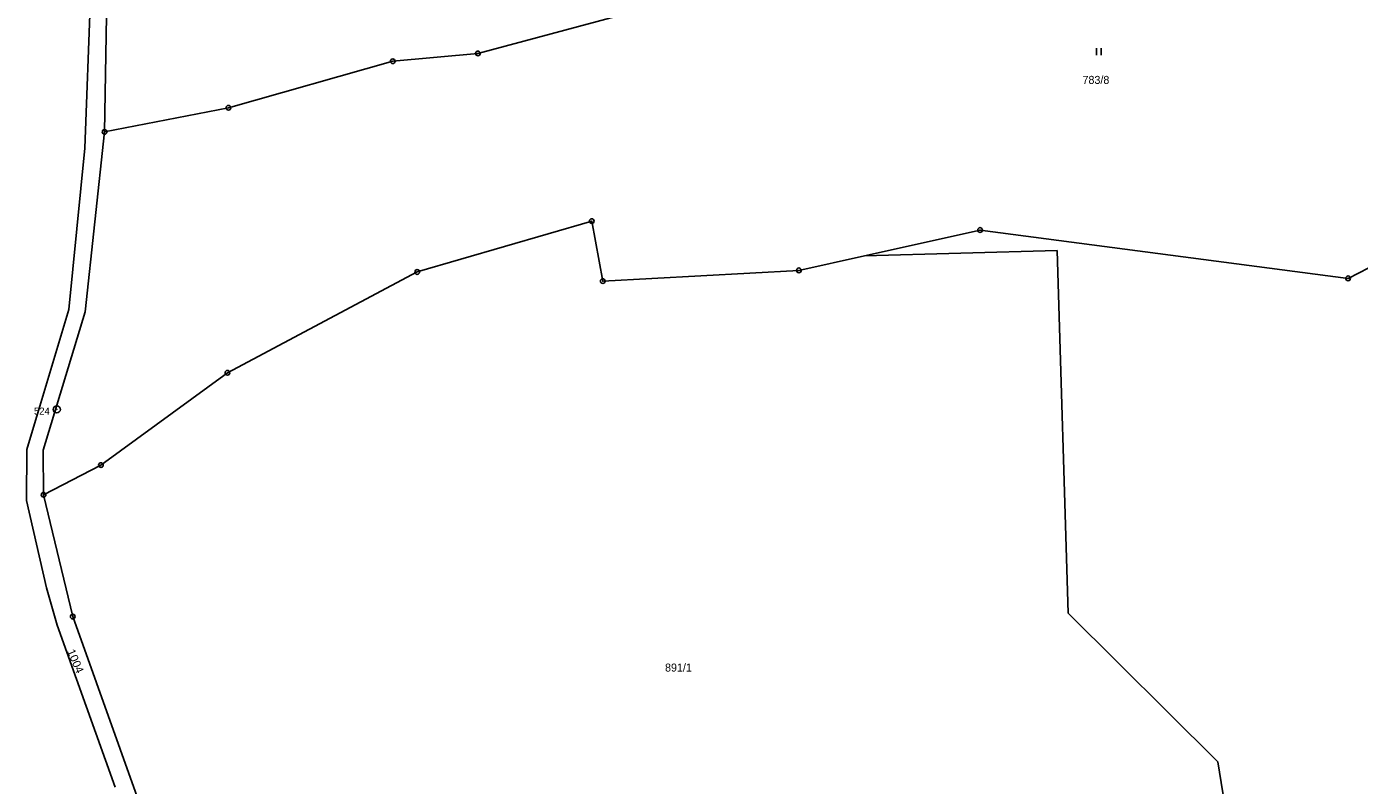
# Model space of a CAD drawing. Extents: x -754970 to -752637, y -970569 to -968179.
# Drawn here: x -754082.5 to -753799.4, y -970155.3 to -969994.1 of the extents above; entities that cross this region are included whole.
import ezdxf
from ezdxf.enums import TextEntityAlignment as Align

# ---------------------------------------------------------------- set-up
doc = ezdxf.new("R2010")
doc.units = 0
doc.header["$LTSCALE"] = 0.68
for name, color, linetype, lineweight in [('1', 7, 'Continuous', 25), ('3', 7, 'Continuous', 25), ('8', 7, 'Continuous', 25)]:
    doc.layers.add(name, color=color, linetype=linetype, lineweight=lineweight)
doc.layers.add('2', color=7, linetype='Continuous')

msp = doc.modelspace()

# ---------------------------------------------------------------- linework, layer by layer
at = {"layer": '1'}
for p, q in [((-754070.1, -970019.91), (-754068.6, -969979.64)), ((-754065.25, -969978.75), (-754065.92, -970016.48)), ((-753955.45, -969991.45), (-753986.6, -969999.8)), ((-753986.6, -969999.8), (-754004.71, -970001.45)), ((-754004.71, -970001.45), (-754039.6, -970011.35)), ((-754039.6, -970011.35), (-754065.92, -970016.48)), ((-754065.92, -970016.48), (-754070.03, -970054.73)), ((-754073.52, -970054.18), (-754070.1, -970019.91)), ((-753999.51, -970046.24), (-753962.42, -970035.44)), ((-753962.42, -970035.44), (-753960.08, -970048.18)), ((-753904.51, -970042.79), (-753879.94, -970037.32)), ((-753879.94, -970037.32), (-753801.75, -970047.59)), ((-753801.75, -970047.59), (-753777.76, -970035.24)), ((-753918.42, -970045.89), (-753904.51, -970042.79)), ((-753904.51, -970042.79), (-753863.57, -970041.64)), ((-753863.57, -970041.64), (-753861.2, -970118.73)), ((-753960.08, -970048.18), (-753918.42, -970045.89)), ((-754039.81, -970067.65), (-753999.51, -970046.24)), ((-754082.4, -970083.94), (-754073.52, -970054.18)), ((-754070.03, -970054.73), (-754078.94, -970084.08)), ((-754066.69, -970087.27), (-754039.81, -970067.65)), ((-754082.47, -970094.81), (-754082.4, -970083.94)), ((-754078.94, -970084.08), (-754078.87, -970093.58)), ((-754078.87, -970093.58), (-754066.69, -970087.27)), ((-754078.87, -970093.58), (-754072.67, -970119.47)), ((-754078.23, -970113.35), (-754082.47, -970094.81)), ((-754075.98, -970121.29), (-754078.23, -970113.35)), ((-754072.67, -970119.47), (-754056.77, -970163.84)), ((-753861.2, -970118.73), (-753829.44, -970150.3)), ((-754063.67, -970155.69), (-754075.98, -970121.29)), ((-753829.44, -970150.3), (-753823.24, -970187.77))]:
    msp.add_line(p, q, dxfattribs=at)
at = {"layer": '3'}
for p, q in [((-753855.221, -970000.2), (-753855.221, -969998.7)), ((-753854.22, -970000.2), (-753854.22, -969998.7))]:
    msp.add_line(p, q, dxfattribs=at)
at = {"layer": '8'}
for centre, radius in [((-753986.6, -969999.7999), 0.5), ((-753986.6, -969999.7999), 0.0303), ((-754004.71, -970001.4499), 0.5), ((-754004.71, -970001.4499), 0.0303), ((-754039.6, -970011.3499), 0.5), ((-754039.6, -970011.3499), 0.0303), ((-754065.92, -970016.4799), 0.5), ((-754065.92, -970016.4799), 0.0303), ((-753962.42, -970035.4399), 0.5), ((-753962.42, -970035.4399), 0.0303), ((-753879.94, -970037.3199), 0.5), ((-753879.94, -970037.3199), 0.0303), ((-753999.51, -970046.2399), 0.5), ((-753918.42, -970045.8899), 0.5), ((-753918.42, -970045.8899), 0.0303), ((-753999.51, -970046.2399), 0.0303), ((-753960.08, -970048.1799), 0.5), ((-753960.08, -970048.1799), 0.0303), ((-753801.75, -970047.5899), 0.5), ((-753801.75, -970047.5899), 0.0303), ((-754039.81, -970067.6499), 0.5), ((-754039.81, -970067.6499), 0.0303), ((-754076.06, -970075.4298), 0.75), ((-754076.06, -970075.4298), 0.03), ((-754066.69, -970087.2699), 0.5), ((-754066.69, -970087.2699), 0.0303), ((-754078.87, -970093.5799), 0.5), ((-754078.87, -970093.5799), 0.0303), ((-754072.67, -970119.4699), 0.5), ((-754072.67, -970119.4699), 0.0303)]:
    msp.add_circle(centre, radius, dxfattribs=at)

# ---------------------------------------------------------------- texts
at = {"layer": '2'}
for s, p in [('783/8', (-753855.32, -970006.275)), ('891/1', (-753944.01, -970131.135))]:
    msp.add_text(s, height=1.7, dxfattribs=at).set_placement(p, align=Align.CENTER)
at = {"layer": '2', "width": 1.05}
msp.add_text('1004', height=1.7, rotation=293, dxfattribs=at).set_placement((-754072.8691, -970129.2349), align=Align.CENTER)
at = {"layer": '8'}
msp.add_text('524', height=1.5, dxfattribs=at).set_placement((-754077.559, -970076.547), align=Align.RIGHT)

doc.saveas('drawing.dxf')
